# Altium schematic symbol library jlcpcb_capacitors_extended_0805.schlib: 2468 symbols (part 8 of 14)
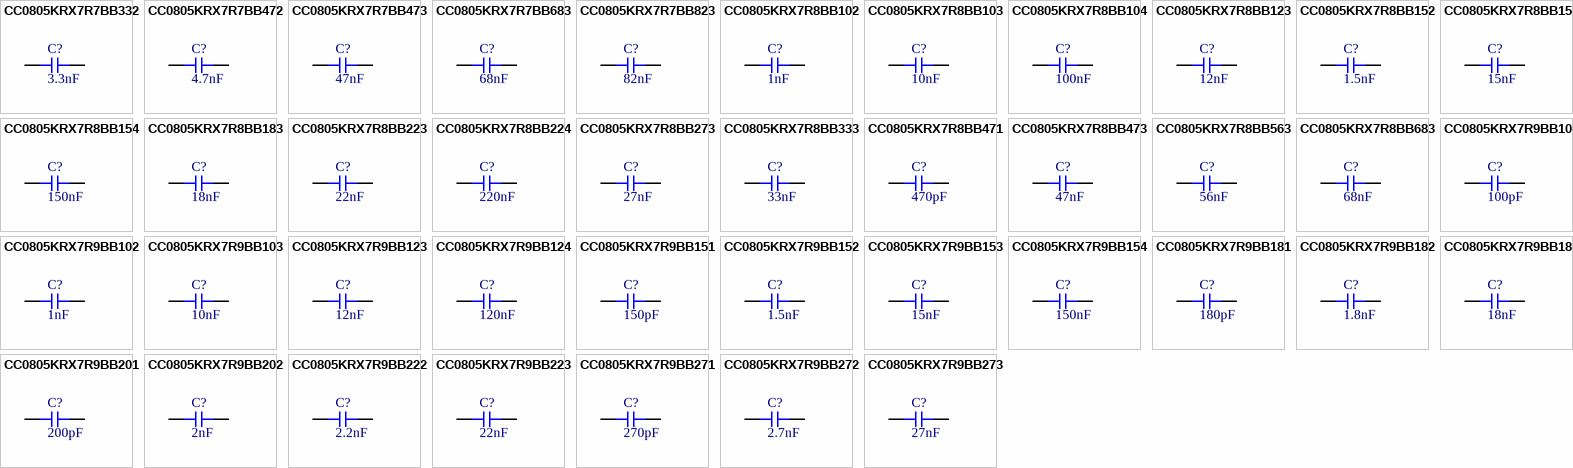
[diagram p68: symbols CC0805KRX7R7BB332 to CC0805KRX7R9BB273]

## CC0805KRX7R8BB102
designator C?  Capacitance: 1nF  (hidden comment: *)
Capacitor, Ceramic (MLCC), 1nF, ±10%, 25V, X7R, ±10%, SMD 0805; Manufacturer: YAGEO; Manufacturer Part Number: CC0805KRX7R8BB102
footprint CAP-0805 (0805 (2012M) Capacitor)
pins: 1, 2

## CC0805KRX7R8BB103
designator C?  Capacitance: 10nF  (hidden comment: *)
Capacitor, Ceramic (MLCC), 10nF, ±10%, 25V, X7R, ±10%, SMD 0805; Manufacturer: YAGEO; Manufacturer Part Number: CC0805KRX7R8BB103
footprint CAP-0805 (0805 (2012M) Capacitor)
pins: 1, 2

## CC0805KRX7R8BB104
designator C?  Capacitance: 100nF  (hidden comment: *)
Capacitor, Ceramic (MLCC), 100nF, ±10%, 25V, X7R, ±10%, SMD 0805; Manufacturer: YAGEO; Manufacturer Part Number: CC0805KRX7R8BB104
footprint CAP-0805 (0805 (2012M) Capacitor)
pins: 1, 2

## CC0805KRX7R8BB123
designator C?  Capacitance: 12nF  (hidden comment: *)
Capacitor, Ceramic (MLCC), 12nF, ±10%, 25V, X7R, ±10%, SMD 0805; Manufacturer: YAGEO; Manufacturer Part Number: CC0805KRX7R8BB123
footprint CAP-0805 (0805 (2012M) Capacitor)
pins: 1, 2

## CC0805KRX7R8BB152
designator C?  Capacitance: 1.5nF  (hidden comment: *)
Capacitor, Ceramic (MLCC), 1.5nF, ±10%, 25V, X7R, ±10%, SMD 0805; Manufacturer: YAGEO; Manufacturer Part Number: CC0805KRX7R8BB152
footprint CAP-0805 (0805 (2012M) Capacitor)
pins: 1, 2

## CC0805KRX7R8BB153
designator C?  Capacitance: 15nF  (hidden comment: *)
Capacitor, Ceramic (MLCC), 15nF, ±10%, 25V, X7R, ±10%, SMD 0805; Manufacturer: YAGEO; Manufacturer Part Number: CC0805KRX7R8BB153
footprint CAP-0805 (0805 (2012M) Capacitor)
pins: 1, 2

## CC0805KRX7R8BB154
designator C?  Capacitance: 150nF  (hidden comment: *)
Capacitor, Ceramic (MLCC), 150nF, ±10%, 25V, X7R, ±10%, SMD 0805; Manufacturer: YAGEO; Manufacturer Part Number: CC0805KRX7R8BB154
footprint CAP-0805 (0805 (2012M) Capacitor)
pins: 1, 2

## CC0805KRX7R8BB183
designator C?  Capacitance: 18nF  (hidden comment: *)
Capacitor, Ceramic (MLCC), 18nF, ±10%, 25V, X7R, ±10%, SMD 0805; Manufacturer: YAGEO; Manufacturer Part Number: CC0805KRX7R8BB183
footprint CAP-0805 (0805 (2012M) Capacitor)
pins: 1, 2

## CC0805KRX7R8BB223
designator C?  Capacitance: 22nF  (hidden comment: *)
Capacitor, Ceramic (MLCC), 22nF, ±10%, 25V, X7R, ±10%, SMD 0805; Manufacturer: YAGEO; Manufacturer Part Number: CC0805KRX7R8BB223
footprint CAP-0805 (0805 (2012M) Capacitor)
pins: 1, 2

## CC0805KRX7R8BB224
designator C?  Capacitance: 220nF  (hidden comment: *)
Capacitor, Ceramic (MLCC), 220nF, ±10%, 25V, X7R, ±10%, SMD 0805; Manufacturer: YAGEO; Manufacturer Part Number: CC0805KRX7R8BB224
footprint CAP-0805 (0805 (2012M) Capacitor)
pins: 1, 2

## CC0805KRX7R8BB273
designator C?  Capacitance: 27nF  (hidden comment: *)
Capacitor, Ceramic (MLCC), 27nF, ±10%, 25V, X7R, ±10%, SMD 0805; Manufacturer: YAGEO; Manufacturer Part Number: CC0805KRX7R8BB273
footprint CAP-0805 (0805 (2012M) Capacitor)
pins: 1, 2

## CC0805KRX7R8BB333
designator C?  Capacitance: 33nF  (hidden comment: *)
Capacitor, Ceramic (MLCC), 33nF, ±10%, 25V, X7R, ±10%, SMD 0805; Manufacturer: YAGEO; Manufacturer Part Number: CC0805KRX7R8BB333
footprint CAP-0805 (0805 (2012M) Capacitor)
pins: 1, 2

## CC0805KRX7R8BB471
designator C?  Capacitance: 470pF  (hidden comment: *)
Capacitor, Ceramic (MLCC), 470pF, ±10%, 25V, X7R, ±10%, SMD 0805; Manufacturer: YAGEO; Manufacturer Part Number: CC0805KRX7R8BB471
footprint CAP-0805 (0805 (2012M) Capacitor)
pins: 1, 2

## CC0805KRX7R8BB473
designator C?  Capacitance: 47nF  (hidden comment: *)
Capacitor, Ceramic (MLCC), 47nF, ±10%, 25V, X7R, ±10%, SMD 0805; Manufacturer: YAGEO; Manufacturer Part Number: CC0805KRX7R8BB473
footprint CAP-0805 (0805 (2012M) Capacitor)
pins: 1, 2

## CC0805KRX7R8BB563
designator C?  Capacitance: 56nF  (hidden comment: *)
Capacitor, Ceramic (MLCC), 56nF, ±10%, 25V, X7R, ±10%, SMD 0805; Manufacturer: YAGEO; Manufacturer Part Number: CC0805KRX7R8BB563
footprint CAP-0805 (0805 (2012M) Capacitor)
pins: 1, 2

## CC0805KRX7R8BB683
designator C?  Capacitance: 68nF  (hidden comment: *)
Capacitor, Ceramic (MLCC), 68nF, ±10%, 25V, X7R, ±10%, SMD 0805; Manufacturer: YAGEO; Manufacturer Part Number: CC0805KRX7R8BB683
footprint CAP-0805 (0805 (2012M) Capacitor)
pins: 1, 2

## CC0805KRX7R9BB101
designator C?  Capacitance: 100pF  (hidden comment: *)
Capacitor, Ceramic (MLCC), 100pF, ±10%, 50V, X7R, ±10%, SMD 0805; Manufacturer: YAGEO; Manufacturer Part Number: CC0805KRX7R9BB101
footprint CAP-0805 (0805 (2012M) Capacitor)
pins: 1, 2

## CC0805KRX7R9BB102
designator C?  Capacitance: 1nF  (hidden comment: *)
Capacitor, Ceramic (MLCC), 1nF, ±10%, 50V, X7R, ±10%, SMD 0805; Manufacturer: YAGEO; Manufacturer Part Number: CC0805KRX7R9BB102
footprint CAP-0805 (0805 (2012M) Capacitor)
pins: 1, 2

## CC0805KRX7R9BB103
designator C?  Capacitance: 10nF  (hidden comment: *)
Capacitor, Ceramic (MLCC), 10nF, ±10%, 50V, X7R, ±10%, SMD 0805; Manufacturer: YAGEO; Manufacturer Part Number: CC0805KRX7R9BB103
footprint CAP-0805 (0805 (2012M) Capacitor)
pins: 1, 2

## CC0805KRX7R9BB123
designator C?  Capacitance: 12nF  (hidden comment: *)
Capacitor, Ceramic (MLCC), 12nF, ±10%, 50V, X7R, ±10%, SMD 0805; Manufacturer: YAGEO; Manufacturer Part Number: CC0805KRX7R9BB123
footprint CAP-0805 (0805 (2012M) Capacitor)
pins: 1, 2

## CC0805KRX7R9BB124
designator C?  Capacitance: 120nF  (hidden comment: *)
Capacitor, Ceramic (MLCC), 120nF, ±10%, 50V, X7R, ±10%, SMD 0805; Manufacturer: YAGEO; Manufacturer Part Number: CC0805KRX7R9BB124
footprint CAP-0805 (0805 (2012M) Capacitor)
pins: 1, 2

## CC0805KRX7R9BB151
designator C?  Capacitance: 150pF  (hidden comment: *)
Capacitor, Ceramic (MLCC), 150pF, ±10%, 50V, X7R, ±10%, SMD 0805; Manufacturer: YAGEO; Manufacturer Part Number: CC0805KRX7R9BB151
footprint CAP-0805 (0805 (2012M) Capacitor)
pins: 1, 2

## CC0805KRX7R9BB152
designator C?  Capacitance: 1.5nF  (hidden comment: *)
Capacitor, Ceramic (MLCC), 1.5nF, ±10%, 50V, X7R, ±10%, SMD 0805; Manufacturer: YAGEO; Manufacturer Part Number: CC0805KRX7R9BB152
footprint CAP-0805 (0805 (2012M) Capacitor)
pins: 1, 2

## CC0805KRX7R9BB153
designator C?  Capacitance: 15nF  (hidden comment: *)
Capacitor, Ceramic (MLCC), 15nF, ±10%, 50V, X7R, ±10%, SMD 0805; Manufacturer: YAGEO; Manufacturer Part Number: CC0805KRX7R9BB153
footprint CAP-0805 (0805 (2012M) Capacitor)
pins: 1, 2

## CC0805KRX7R9BB154
designator C?  Capacitance: 150nF  (hidden comment: *)
Capacitor, Ceramic (MLCC), 150nF, ±10%, 50V, X7R, ±10%, SMD 0805; Manufacturer: YAGEO; Manufacturer Part Number: CC0805KRX7R9BB154
footprint CAP-0805 (0805 (2012M) Capacitor)
pins: 1, 2

## CC0805KRX7R9BB181
designator C?  Capacitance: 180pF  (hidden comment: *)
Capacitor, Ceramic (MLCC), 180pF, ±10%, 50V, X7R, ±10%, SMD 0805; Manufacturer: YAGEO; Manufacturer Part Number: CC0805KRX7R9BB181
footprint CAP-0805 (0805 (2012M) Capacitor)
pins: 1, 2

## CC0805KRX7R9BB182
designator C?  Capacitance: 1.8nF  (hidden comment: *)
Capacitor, Ceramic (MLCC), 1.8nF, ±10%, 50V, X7R, ±10%, SMD 0805; Manufacturer: YAGEO; Manufacturer Part Number: CC0805KRX7R9BB182
footprint CAP-0805 (0805 (2012M) Capacitor)
pins: 1, 2

## CC0805KRX7R9BB183
designator C?  Capacitance: 18nF  (hidden comment: *)
Capacitor, Ceramic (MLCC), 18nF, ±10%, 50V, X7R, ±10%, SMD 0805; Manufacturer: YAGEO; Manufacturer Part Number: CC0805KRX7R9BB183
footprint CAP-0805 (0805 (2012M) Capacitor)
pins: 1, 2

## CC0805KRX7R9BB201
designator C?  Capacitance: 200pF  (hidden comment: *)
Capacitor, Ceramic (MLCC), 200pF, ±10%, 50V, X7R, ±10%, SMD 0805; Manufacturer: YAGEO; Manufacturer Part Number: CC0805KRX7R9BB201
footprint CAP-0805 (0805 (2012M) Capacitor)
pins: 1, 2

## CC0805KRX7R9BB202
designator C?  Capacitance: 2nF  (hidden comment: *)
Capacitor, Ceramic (MLCC), 2nF, ±10%, 50V, X7R, ±10%, SMD 0805; Manufacturer: YAGEO; Manufacturer Part Number: CC0805KRX7R9BB202
footprint CAP-0805 (0805 (2012M) Capacitor)
pins: 1, 2

## CC0805KRX7R9BB222
designator C?  Capacitance: 2.2nF  (hidden comment: *)
Capacitor, Ceramic (MLCC), 2.2nF, ±10%, 50V, X7R, ±10%, SMD 0805; Manufacturer: YAGEO; Manufacturer Part Number: CC0805KRX7R9BB222
footprint CAP-0805 (0805 (2012M) Capacitor)
pins: 1, 2

## CC0805KRX7R9BB223
designator C?  Capacitance: 22nF  (hidden comment: *)
Capacitor, Ceramic (MLCC), 22nF, ±10%, 50V, X7R, ±10%, SMD 0805; Manufacturer: YAGEO; Manufacturer Part Number: CC0805KRX7R9BB223
footprint CAP-0805 (0805 (2012M) Capacitor)
pins: 1, 2

## CC0805KRX7R9BB271
designator C?  Capacitance: 270pF  (hidden comment: *)
Capacitor, Ceramic (MLCC), 270pF, ±10%, 50V, X7R, ±10%, SMD 0805; Manufacturer: YAGEO; Manufacturer Part Number: CC0805KRX7R9BB271
footprint CAP-0805 (0805 (2012M) Capacitor)
pins: 1, 2

## CC0805KRX7R9BB272
designator C?  Capacitance: 2.7nF  (hidden comment: *)
Capacitor, Ceramic (MLCC), 2.7nF, ±10%, 50V, X7R, ±10%, SMD 0805; Manufacturer: YAGEO; Manufacturer Part Number: CC0805KRX7R9BB272
footprint CAP-0805 (0805 (2012M) Capacitor)
pins: 1, 2

## CC0805KRX7R9BB273
designator C?  Capacitance: 27nF  (hidden comment: *)
Capacitor, Ceramic (MLCC), 27nF, ±10%, 50V, X7R, ±10%, SMD 0805; Manufacturer: YAGEO; Manufacturer Part Number: CC0805KRX7R9BB273
footprint CAP-0805 (0805 (2012M) Capacitor)
pins: 1, 2

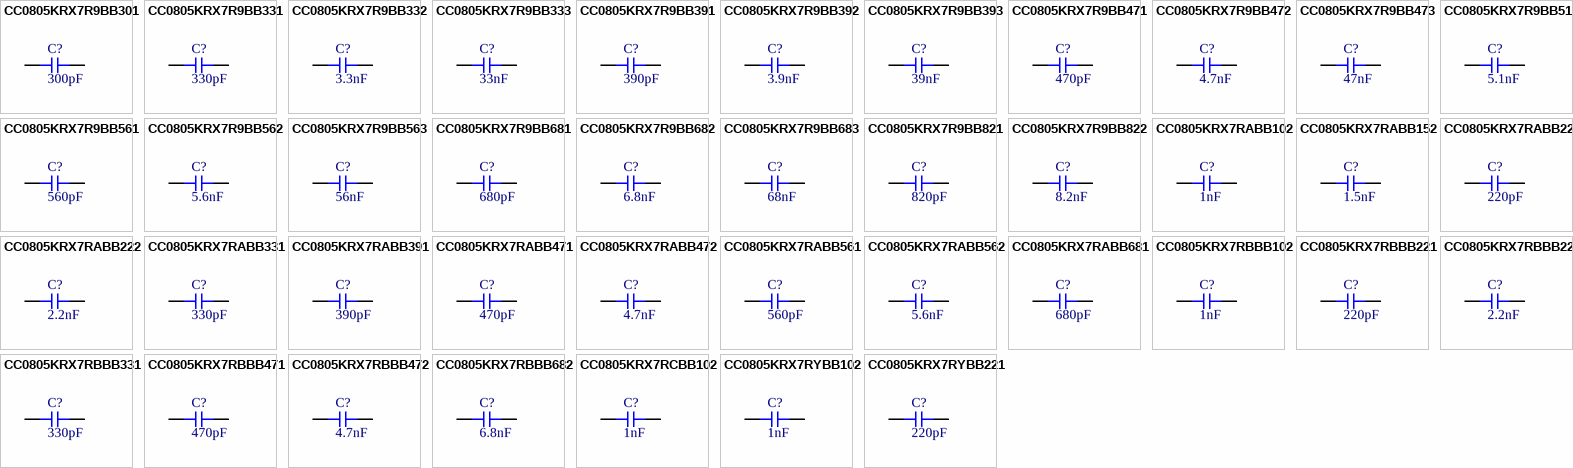
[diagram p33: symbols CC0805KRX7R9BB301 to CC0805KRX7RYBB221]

## CC0805KRX7R9BB301
designator C?  Capacitance: 300pF  (hidden comment: *)
Capacitor, Ceramic (MLCC), 300pF, ±10%, 50V, X7R, ±10%, SMD 0805; Manufacturer: YAGEO; Manufacturer Part Number: CC0805KRX7R9BB301
footprint CAP-0805 (0805 (2012M) Capacitor)
pins: 1, 2

## CC0805KRX7R9BB331
designator C?  Capacitance: 330pF  (hidden comment: *)
Capacitor, Ceramic (MLCC), 330pF, ±10%, 50V, X7R, ±10%, SMD 0805; Manufacturer: YAGEO; Manufacturer Part Number: CC0805KRX7R9BB331
footprint CAP-0805 (0805 (2012M) Capacitor)
pins: 1, 2

## CC0805KRX7R9BB332
designator C?  Capacitance: 3.3nF  (hidden comment: *)
Capacitor, Ceramic (MLCC), 3.3nF, ±10%, 50V, X7R, ±10%, SMD 0805; Manufacturer: YAGEO; Manufacturer Part Number: CC0805KRX7R9BB332
footprint CAP-0805 (0805 (2012M) Capacitor)
pins: 1, 2

## CC0805KRX7R9BB333
designator C?  Capacitance: 33nF  (hidden comment: *)
Capacitor, Ceramic (MLCC), 33nF, ±10%, 50V, X7R, ±10%, SMD 0805; Manufacturer: YAGEO; Manufacturer Part Number: CC0805KRX7R9BB333
footprint CAP-0805 (0805 (2012M) Capacitor)
pins: 1, 2

## CC0805KRX7R9BB391
designator C?  Capacitance: 390pF  (hidden comment: *)
Capacitor, Ceramic (MLCC), 390pF, ±10%, 50V, X7R, ±10%, SMD 0805; Manufacturer: YAGEO; Manufacturer Part Number: CC0805KRX7R9BB391
footprint CAP-0805 (0805 (2012M) Capacitor)
pins: 1, 2

## CC0805KRX7R9BB392
designator C?  Capacitance: 3.9nF  (hidden comment: *)
Capacitor, Ceramic (MLCC), 3.9nF, ±10%, 50V, X7R, ±10%, SMD 0805; Manufacturer: YAGEO; Manufacturer Part Number: CC0805KRX7R9BB392
footprint CAP-0805 (0805 (2012M) Capacitor)
pins: 1, 2

## CC0805KRX7R9BB393
designator C?  Capacitance: 39nF  (hidden comment: *)
Capacitor, Ceramic (MLCC), 39nF, ±10%, 50V, X7R, ±10%, SMD 0805; Manufacturer: YAGEO; Manufacturer Part Number: CC0805KRX7R9BB393
footprint CAP-0805 (0805 (2012M) Capacitor)
pins: 1, 2

## CC0805KRX7R9BB471
designator C?  Capacitance: 470pF  (hidden comment: *)
Capacitor, Ceramic (MLCC), 470pF, ±10%, 50V, X7R, ±10%, SMD 0805; Manufacturer: YAGEO; Manufacturer Part Number: CC0805KRX7R9BB471
footprint CAP-0805 (0805 (2012M) Capacitor)
pins: 1, 2

## CC0805KRX7R9BB472
designator C?  Capacitance: 4.7nF  (hidden comment: *)
Capacitor, Ceramic (MLCC), 4.7nF, ±10%, 50V, X7R, ±10%, SMD 0805; Manufacturer: YAGEO; Manufacturer Part Number: CC0805KRX7R9BB472
footprint CAP-0805 (0805 (2012M) Capacitor)
pins: 1, 2

## CC0805KRX7R9BB473
designator C?  Capacitance: 47nF  (hidden comment: *)
Capacitor, Ceramic (MLCC), 47nF, ±10%, 50V, X7R, ±10%, SMD 0805; Manufacturer: YAGEO; Manufacturer Part Number: CC0805KRX7R9BB473
footprint CAP-0805 (0805 (2012M) Capacitor)
pins: 1, 2

## CC0805KRX7R9BB512
designator C?  Capacitance: 5.1nF  (hidden comment: *)
Capacitor, Ceramic (MLCC), 5.1nF, ±10%, 50V, X7R, ±10%, SMD 0805; Manufacturer: YAGEO; Manufacturer Part Number: CC0805KRX7R9BB512
footprint CAP-0805 (0805 (2012M) Capacitor)
pins: 1, 2

## CC0805KRX7R9BB561
designator C?  Capacitance: 560pF  (hidden comment: *)
Capacitor, Ceramic (MLCC), 560pF, ±10%, 50V, X7R, ±10%, SMD 0805; Manufacturer: YAGEO; Manufacturer Part Number: CC0805KRX7R9BB561
footprint CAP-0805 (0805 (2012M) Capacitor)
pins: 1, 2

## CC0805KRX7R9BB562
designator C?  Capacitance: 5.6nF  (hidden comment: *)
Capacitor, Ceramic (MLCC), 5.6nF, ±10%, 50V, X7R, ±10%, SMD 0805; Manufacturer: YAGEO; Manufacturer Part Number: CC0805KRX7R9BB562
footprint CAP-0805 (0805 (2012M) Capacitor)
pins: 1, 2

## CC0805KRX7R9BB563
designator C?  Capacitance: 56nF  (hidden comment: *)
Capacitor, Ceramic (MLCC), 56nF, ±10%, 50V, X7R, ±10%, SMD 0805; Manufacturer: YAGEO; Manufacturer Part Number: CC0805KRX7R9BB563
footprint CAP-0805 (0805 (2012M) Capacitor)
pins: 1, 2

## CC0805KRX7R9BB681
designator C?  Capacitance: 680pF  (hidden comment: *)
Capacitor, Ceramic (MLCC), 680pF, ±10%, 50V, X7R, ±10%, SMD 0805; Manufacturer: YAGEO; Manufacturer Part Number: CC0805KRX7R9BB681
footprint CAP-0805 (0805 (2012M) Capacitor)
pins: 1, 2

## CC0805KRX7R9BB682
designator C?  Capacitance: 6.8nF  (hidden comment: *)
Capacitor, Ceramic (MLCC), 6.8nF, ±10%, 50V, X7R, ±10%, SMD 0805; Manufacturer: YAGEO; Manufacturer Part Number: CC0805KRX7R9BB682
footprint CAP-0805 (0805 (2012M) Capacitor)
pins: 1, 2

## CC0805KRX7R9BB683
designator C?  Capacitance: 68nF  (hidden comment: *)
Capacitor, Ceramic (MLCC), 68nF, ±10%, 50V, X7R, ±10%, SMD 0805; Manufacturer: YAGEO; Manufacturer Part Number: CC0805KRX7R9BB683
footprint CAP-0805 (0805 (2012M) Capacitor)
pins: 1, 2

## CC0805KRX7R9BB821
designator C?  Capacitance: 820pF  (hidden comment: *)
Capacitor, Ceramic (MLCC), 820pF, ±10%, 50V, X7R, ±10%, SMD 0805; Manufacturer: YAGEO; Manufacturer Part Number: CC0805KRX7R9BB821
footprint CAP-0805 (0805 (2012M) Capacitor)
pins: 1, 2

## CC0805KRX7R9BB822
designator C?  Capacitance: 8.2nF  (hidden comment: *)
Capacitor, Ceramic (MLCC), 8.2nF, ±10%, 50V, X7R, ±10%, SMD 0805; Manufacturer: YAGEO; Manufacturer Part Number: CC0805KRX7R9BB822
footprint CAP-0805 (0805 (2012M) Capacitor)
pins: 1, 2

## CC0805KRX7RABB102
designator C?  Capacitance: 1nF  (hidden comment: *)
Capacitor, Ceramic (MLCC), 1nF, ±10%, 200V, X7R, ±10%, SMD 0805; Manufacturer: YAGEO; Manufacturer Part Number: CC0805KRX7RABB102
footprint CAP-0805 (0805 (2012M) Capacitor)
pins: 1, 2

## CC0805KRX7RABB152
designator C?  Capacitance: 1.5nF  (hidden comment: *)
Capacitor, Ceramic (MLCC), 1.5nF, ±10%, 200V, X7R, ±10%, SMD 0805; Manufacturer: YAGEO; Manufacturer Part Number: CC0805KRX7RABB152
footprint CAP-0805 (0805 (2012M) Capacitor)
pins: 1, 2

## CC0805KRX7RABB221
designator C?  Capacitance: 220pF  (hidden comment: *)
Capacitor, Ceramic (MLCC), 220pF, ±10%, 200V, X7R, ±10%, SMD 0805; Manufacturer: YAGEO; Manufacturer Part Number: CC0805KRX7RABB221
footprint CAP-0805 (0805 (2012M) Capacitor)
pins: 1, 2

## CC0805KRX7RABB222
designator C?  Capacitance: 2.2nF  (hidden comment: *)
Capacitor, Ceramic (MLCC), 2.2nF, ±10%, 200V, X7R, ±10%, SMD 0805; Manufacturer: YAGEO; Manufacturer Part Number: CC0805KRX7RABB222
footprint CAP-0805 (0805 (2012M) Capacitor)
pins: 1, 2

## CC0805KRX7RABB331
designator C?  Capacitance: 330pF  (hidden comment: *)
Capacitor, Ceramic (MLCC), 330pF, ±10%, 200V, X7R, ±10%, SMD 0805; Manufacturer: YAGEO; Manufacturer Part Number: CC0805KRX7RABB331
footprint CAP-0805 (0805 (2012M) Capacitor)
pins: 1, 2

## CC0805KRX7RABB391
designator C?  Capacitance: 390pF  (hidden comment: *)
Capacitor, Ceramic (MLCC), 390pF, ±10%, 200V, X7R, ±10%, SMD 0805; Manufacturer: YAGEO; Manufacturer Part Number: CC0805KRX7RABB391
footprint CAP-0805 (0805 (2012M) Capacitor)
pins: 1, 2

## CC0805KRX7RABB471
designator C?  Capacitance: 470pF  (hidden comment: *)
Capacitor, Ceramic (MLCC), 470pF, ±10%, 200V, X7R, ±10%, SMD 0805; Manufacturer: YAGEO; Manufacturer Part Number: CC0805KRX7RABB471
footprint CAP-0805 (0805 (2012M) Capacitor)
pins: 1, 2

## CC0805KRX7RABB472
designator C?  Capacitance: 4.7nF  (hidden comment: *)
Capacitor, Ceramic (MLCC), 4.7nF, ±10%, 200V, X7R, ±10%, SMD 0805; Manufacturer: YAGEO; Manufacturer Part Number: CC0805KRX7RABB472
footprint CAP-0805 (0805 (2012M) Capacitor)
pins: 1, 2

## CC0805KRX7RABB561
designator C?  Capacitance: 560pF  (hidden comment: *)
Capacitor, Ceramic (MLCC), 560pF, ±10%, 200V, X7R, ±10%, SMD 0805; Manufacturer: YAGEO; Manufacturer Part Number: CC0805KRX7RABB561
footprint CAP-0805 (0805 (2012M) Capacitor)
pins: 1, 2

## CC0805KRX7RABB562
designator C?  Capacitance: 5.6nF  (hidden comment: *)
Capacitor, Ceramic (MLCC), 5.6nF, ±10%, 200V, X7R, ±10%, SMD 0805; Manufacturer: YAGEO; Manufacturer Part Number: CC0805KRX7RABB562
footprint CAP-0805 (0805 (2012M) Capacitor)
pins: 1, 2

## CC0805KRX7RABB681
designator C?  Capacitance: 680pF  (hidden comment: *)
Capacitor, Ceramic (MLCC), 680pF, ±10%, 200V, X7R, ±10%, SMD 0805; Manufacturer: YAGEO; Manufacturer Part Number: CC0805KRX7RABB681
footprint CAP-0805 (0805 (2012M) Capacitor)
pins: 1, 2

## CC0805KRX7RBBB102
designator C?  Capacitance: 1nF  (hidden comment: *)
Capacitor, Ceramic (MLCC), 1nF, ±10%, 500V, X7R, ±10%, SMD 0805; Manufacturer: YAGEO; Manufacturer Part Number: CC0805KRX7RBBB102
footprint CAP-0805 (0805 (2012M) Capacitor)
pins: 1, 2

## CC0805KRX7RBBB221
designator C?  Capacitance: 220pF  (hidden comment: *)
Capacitor, Ceramic (MLCC), 220pF, ±10%, 500V, X7R, ±10%, SMD 0805; Manufacturer: YAGEO; Manufacturer Part Number: CC0805KRX7RBBB221
footprint CAP-0805 (0805 (2012M) Capacitor)
pins: 1, 2

## CC0805KRX7RBBB222
designator C?  Capacitance: 2.2nF  (hidden comment: *)
Capacitor, Ceramic (MLCC), 2.2nF, ±10%, 500V, X7R, ±10%, SMD 0805; Manufacturer: YAGEO; Manufacturer Part Number: CC0805KRX7RBBB222
footprint CAP-0805 (0805 (2012M) Capacitor)
pins: 1, 2

## CC0805KRX7RBBB331
designator C?  Capacitance: 330pF  (hidden comment: *)
Capacitor, Ceramic (MLCC), 330pF, ±10%, 500V, X7R, ±10%, SMD 0805; Manufacturer: YAGEO; Manufacturer Part Number: CC0805KRX7RBBB331
footprint CAP-0805 (0805 (2012M) Capacitor)
pins: 1, 2

## CC0805KRX7RBBB471
designator C?  Capacitance: 470pF  (hidden comment: *)
Capacitor, Ceramic (MLCC), 470pF, ±10%, 500V, X7R, ±10%, SMD 0805; Manufacturer: YAGEO; Manufacturer Part Number: CC0805KRX7RBBB471
footprint CAP-0805 (0805 (2012M) Capacitor)
pins: 1, 2

## CC0805KRX7RBBB472
designator C?  Capacitance: 4.7nF  (hidden comment: *)
Capacitor, Ceramic (MLCC), 4.7nF, ±10%, 500V, X7R, ±10%, SMD 0805; Manufacturer: YAGEO; Manufacturer Part Number: CC0805KRX7RBBB472
footprint CAP-0805 (0805 (2012M) Capacitor)
pins: 1, 2

## CC0805KRX7RBBB682
designator C?  Capacitance: 6.8nF  (hidden comment: *)
Capacitor, Ceramic (MLCC), 6.8nF, ±10%, 500V, X7R, ±10%, SMD 0805; Manufacturer: YAGEO; Manufacturer Part Number: CC0805KRX7RBBB682
footprint CAP-0805 (0805 (2012M) Capacitor)
pins: 1, 2

## CC0805KRX7RCBB102
designator C?  Capacitance: 1nF  (hidden comment: *)
Capacitor, Ceramic (MLCC), 1nF, ±10%, 1kV, X7R, ±10%, SMD 0805; Manufacturer: YAGEO; Manufacturer Part Number: CC0805KRX7RCBB102
footprint CAP-0805 (0805 (2012M) Capacitor)
pins: 1, 2

## CC0805KRX7RYBB102
designator C?  Capacitance: 1nF  (hidden comment: *)
Capacitor, Ceramic (MLCC), 1nF, ±10%, 250V, X7R, ±10%, SMD 0805; Manufacturer: YAGEO; Manufacturer Part Number: CC0805KRX7RYBB102
footprint CAP-0805 (0805 (2012M) Capacitor)
pins: 1, 2

## CC0805KRX7RYBB221
designator C?  Capacitance: 220pF  (hidden comment: *)
Capacitor, Ceramic (MLCC), 220pF, ±10%, 250V, X7R, ±10%, SMD 0805; Manufacturer: YAGEO; Manufacturer Part Number: CC0805KRX7RYBB221
footprint CAP-0805 (0805 (2012M) Capacitor)
pins: 1, 2

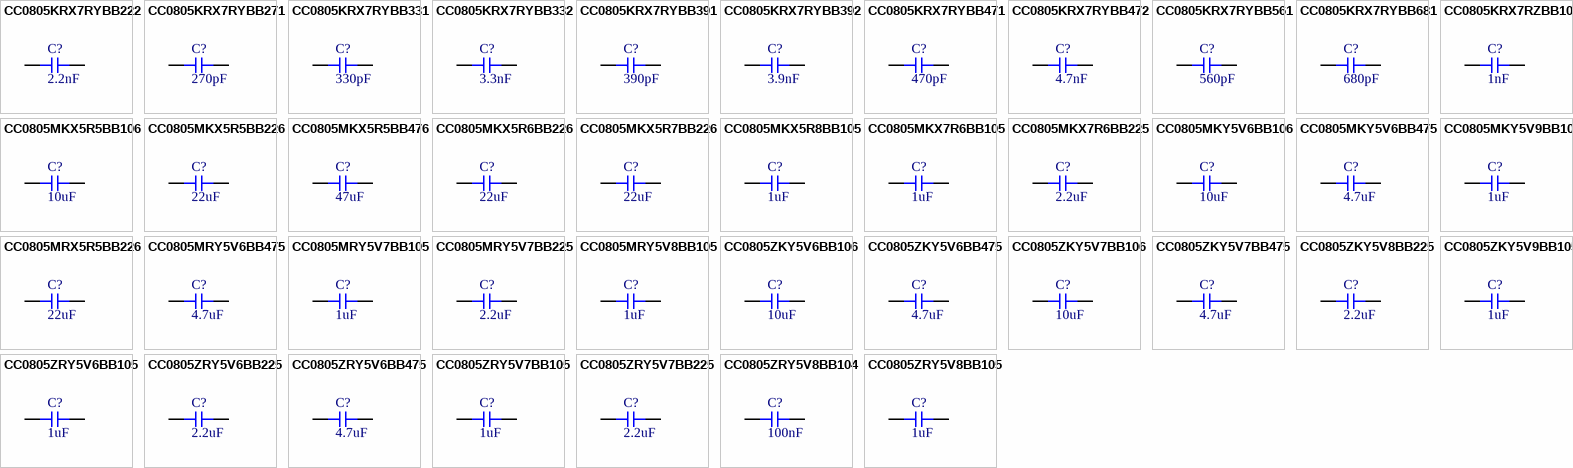
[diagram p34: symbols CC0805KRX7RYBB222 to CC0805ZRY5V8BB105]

## CC0805KRX7RYBB222
designator C?  Capacitance: 2.2nF  (hidden comment: *)
Capacitor, Ceramic (MLCC), 2.2nF, ±10%, 250V, X7R, ±10%, SMD 0805; Manufacturer: YAGEO; Manufacturer Part Number: CC0805KRX7RYBB222
footprint CAP-0805 (0805 (2012M) Capacitor)
pins: 1, 2

## CC0805KRX7RYBB271
designator C?  Capacitance: 270pF  (hidden comment: *)
Capacitor, Ceramic (MLCC), 270pF, ±10%, 250V, X7R, ±10%, SMD 0805; Manufacturer: YAGEO; Manufacturer Part Number: CC0805KRX7RYBB271
footprint CAP-0805 (0805 (2012M) Capacitor)
pins: 1, 2

## CC0805KRX7RYBB331
designator C?  Capacitance: 330pF  (hidden comment: *)
Capacitor, Ceramic (MLCC), 330pF, ±10%, 250V, X7R, ±10%, SMD 0805; Manufacturer: YAGEO; Manufacturer Part Number: CC0805KRX7RYBB331
footprint CAP-0805 (0805 (2012M) Capacitor)
pins: 1, 2

## CC0805KRX7RYBB332
designator C?  Capacitance: 3.3nF  (hidden comment: *)
Capacitor, Ceramic (MLCC), 3.3nF, ±10%, 250V, X7R, ±10%, SMD 0805; Manufacturer: YAGEO; Manufacturer Part Number: CC0805KRX7RYBB332
footprint CAP-0805 (0805 (2012M) Capacitor)
pins: 1, 2

## CC0805KRX7RYBB391
designator C?  Capacitance: 390pF  (hidden comment: *)
Capacitor, Ceramic (MLCC), 390pF, ±10%, 250V, X7R, ±10%, SMD 0805; Manufacturer: YAGEO; Manufacturer Part Number: CC0805KRX7RYBB391
footprint CAP-0805 (0805 (2012M) Capacitor)
pins: 1, 2

## CC0805KRX7RYBB392
designator C?  Capacitance: 3.9nF  (hidden comment: *)
Capacitor, Ceramic (MLCC), 3.9nF, ±10%, 250V, X7R, ±10%, SMD 0805; Manufacturer: YAGEO; Manufacturer Part Number: CC0805KRX7RYBB392
footprint CAP-0805 (0805 (2012M) Capacitor)
pins: 1, 2

## CC0805KRX7RYBB471
designator C?  Capacitance: 470pF  (hidden comment: *)
Capacitor, Ceramic (MLCC), 470pF, ±10%, 250V, X7R, ±10%, SMD 0805; Manufacturer: YAGEO; Manufacturer Part Number: CC0805KRX7RYBB471
footprint CAP-0805 (0805 (2012M) Capacitor)
pins: 1, 2

## CC0805KRX7RYBB472
designator C?  Capacitance: 4.7nF  (hidden comment: *)
Capacitor, Ceramic (MLCC), 4.7nF, ±10%, 250V, X7R, ±10%, SMD 0805; Manufacturer: YAGEO; Manufacturer Part Number: CC0805KRX7RYBB472
footprint CAP-0805 (0805 (2012M) Capacitor)
pins: 1, 2

## CC0805KRX7RYBB561
designator C?  Capacitance: 560pF  (hidden comment: *)
Capacitor, Ceramic (MLCC), 560pF, ±10%, 250V, X7R, ±10%, SMD 0805; Manufacturer: YAGEO; Manufacturer Part Number: CC0805KRX7RYBB561
footprint CAP-0805 (0805 (2012M) Capacitor)
pins: 1, 2

## CC0805KRX7RYBB681
designator C?  Capacitance: 680pF  (hidden comment: *)
Capacitor, Ceramic (MLCC), 680pF, ±10%, 250V, X7R, ±10%, SMD 0805; Manufacturer: YAGEO; Manufacturer Part Number: CC0805KRX7RYBB681
footprint CAP-0805 (0805 (2012M) Capacitor)
pins: 1, 2

## CC0805KRX7RZBB102
designator C?  Capacitance: 1nF  (hidden comment: *)
Capacitor, Ceramic (MLCC), 1nF, ±10%, 630V, X7R, ±10%, SMD 0805; Manufacturer: YAGEO; Manufacturer Part Number: CC0805KRX7RZBB102
footprint CAP-0805 (0805 (2012M) Capacitor)
pins: 1, 2

## CC0805MKX5R5BB106
designator C?  Capacitance: 10uF  (hidden comment: *)
Capacitor, Ceramic (MLCC), 10uF, ±20%, 6.3V, X5R, ±20%, SMD 0805; Manufacturer: YAGEO; Manufacturer Part Number: CC0805MKX5R5BB106
footprint CAP-0805 (0805 (2012M) Capacitor)
pins: 1, 2

## CC0805MKX5R5BB226
designator C?  Capacitance: 22uF  (hidden comment: *)
Capacitor, Ceramic (MLCC), 22uF, ±20%, 6.3V, X5R, ±20%, SMD 0805; Manufacturer: YAGEO; Manufacturer Part Number: CC0805MKX5R5BB226
footprint CAP-0805 (0805 (2012M) Capacitor)
pins: 1, 2

## CC0805MKX5R5BB476
designator C?  Capacitance: 47uF  (hidden comment: *)
Capacitor, Ceramic (MLCC), 47uF, ±20%, 6.3V, X5R, ±20%, SMD 0805; Manufacturer: YAGEO; Manufacturer Part Number: CC0805MKX5R5BB476
footprint CAP-0805 (0805 (2012M) Capacitor)
pins: 1, 2

## CC0805MKX5R6BB226
designator C?  Capacitance: 22uF  (hidden comment: *)
Capacitor, Ceramic (MLCC), 22uF, ±20%, 10V, X5R, ±20%, SMD 0805; Manufacturer: YAGEO; Manufacturer Part Number: CC0805MKX5R6BB226
footprint CAP-0805 (0805 (2012M) Capacitor)
pins: 1, 2

## CC0805MKX5R7BB226
designator C?  Capacitance: 22uF  (hidden comment: *)
Capacitor, Ceramic (MLCC), 22uF, ±20%, 16V, X5R, ±20%, SMD 0805; Manufacturer: YAGEO; Manufacturer Part Number: CC0805MKX5R7BB226
footprint CAP-0805 (0805 (2012M) Capacitor)
pins: 1, 2

## CC0805MKX5R8BB105
designator C?  Capacitance: 1uF  (hidden comment: *)
Capacitor, Ceramic (MLCC), 1uF, ±20%, 25V, X5R, ±20%, SMD 0805; Manufacturer: YAGEO; Manufacturer Part Number: CC0805MKX5R8BB105
footprint CAP-0805 (0805 (2012M) Capacitor)
pins: 1, 2

## CC0805MKX7R6BB105
designator C?  Capacitance: 1uF  (hidden comment: *)
Capacitor, Ceramic (MLCC), 1uF, ±20%, 10V, X7R, ±20%, SMD 0805; Manufacturer: YAGEO; Manufacturer Part Number: CC0805MKX7R6BB105
footprint CAP-0805 (0805 (2012M) Capacitor)
pins: 1, 2

## CC0805MKX7R6BB225
designator C?  Capacitance: 2.2uF  (hidden comment: *)
Capacitor, Ceramic (MLCC), 2.2uF, ±20%, 10V, X7R, ±20%, SMD 0805; Manufacturer: YAGEO; Manufacturer Part Number: CC0805MKX7R6BB225
footprint CAP-0805 (0805 (2012M) Capacitor)
pins: 1, 2

## CC0805MKY5V6BB106
designator C?  Capacitance: 10uF  (hidden comment: *)
Capacitor, Ceramic (MLCC), 10uF, ±20%, 10V, Y5V, ±20%, SMD 0805; Manufacturer: YAGEO; Manufacturer Part Number: CC0805MKY5V6BB106
footprint CAP-0805 (0805 (2012M) Capacitor)
pins: 1, 2

## CC0805MKY5V6BB475
designator C?  Capacitance: 4.7uF  (hidden comment: *)
Capacitor, Ceramic (MLCC), 4.7uF, ±20%, 10V, Y5V, ±20%, SMD 0805; Manufacturer: YAGEO; Manufacturer Part Number: CC0805MKY5V6BB475
footprint CAP-0805 (0805 (2012M) Capacitor)
pins: 1, 2

## CC0805MKY5V9BB105
designator C?  Capacitance: 1uF  (hidden comment: *)
Capacitor, Ceramic (MLCC), 1uF, ±20%, 50V, Y5V, ±20%, SMD 0805; Manufacturer: YAGEO; Manufacturer Part Number: CC0805MKY5V9BB105
footprint CAP-0805 (0805 (2012M) Capacitor)
pins: 1, 2

## CC0805MRX5R5BB226
designator C?  Capacitance: 22uF  (hidden comment: *)
Capacitor, Ceramic (MLCC), 22uF, ±20%, 6.3V, X5R, ±20%, SMD 0805; Manufacturer: YAGEO; Manufacturer Part Number: CC0805MRX5R5BB226
footprint CAP-0805 (0805 (2012M) Capacitor)
pins: 1, 2

## CC0805MRY5V6BB475
designator C?  Capacitance: 4.7uF  (hidden comment: *)
Capacitor, Ceramic (MLCC), 4.7uF, ±20%, 10V, Y5V, ±20%, SMD 0805; Manufacturer: YAGEO; Manufacturer Part Number: CC0805MRY5V6BB475
footprint CAP-0805 (0805 (2012M) Capacitor)
pins: 1, 2

## CC0805MRY5V7BB105
designator C?  Capacitance: 1uF  (hidden comment: *)
Capacitor, Ceramic (MLCC), 1uF, ±20%, 16V, Y5V, ±20%, SMD 0805; Manufacturer: YAGEO; Manufacturer Part Number: CC0805MRY5V7BB105
footprint CAP-0805 (0805 (2012M) Capacitor)
pins: 1, 2

## CC0805MRY5V7BB225
designator C?  Capacitance: 2.2uF  (hidden comment: *)
Capacitor, Ceramic (MLCC), 2.2uF, ±20%, 16V, Y5V, ±20%, SMD 0805; Manufacturer: YAGEO; Manufacturer Part Number: CC0805MRY5V7BB225
footprint CAP-0805 (0805 (2012M) Capacitor)
pins: 1, 2

## CC0805MRY5V8BB105
designator C?  Capacitance: 1uF  (hidden comment: *)
Capacitor, Ceramic (MLCC), 1uF, ±20%, 25V, Y5V, ±20%, SMD 0805; Manufacturer: YAGEO; Manufacturer Part Number: CC0805MRY5V8BB105
footprint CAP-0805 (0805 (2012M) Capacitor)
pins: 1, 2

## CC0805ZKY5V6BB106
designator C?  Capacitance: 10uF  (hidden comment: *)
Capacitor, Ceramic (MLCC), 10uF, 10V, Y5V, SMD 0805; Manufacturer: YAGEO; Manufacturer Part Number: CC0805ZKY5V6BB106; Temperature Rating: -20%~+80%
footprint CAP-0805 (0805 (2012M) Capacitor)
pins: 1, 2

## CC0805ZKY5V6BB475
designator C?  Capacitance: 4.7uF  (hidden comment: *)
Capacitor, Ceramic (MLCC), 4.7uF, 10V, Y5V, SMD 0805; Manufacturer: YAGEO; Manufacturer Part Number: CC0805ZKY5V6BB475; Temperature Rating: -20%~+80%
footprint CAP-0805 (0805 (2012M) Capacitor)
pins: 1, 2

## CC0805ZKY5V7BB106
designator C?  Capacitance: 10uF  (hidden comment: *)
Capacitor, Ceramic (MLCC), 10uF, 16V, Y5V, SMD 0805; Manufacturer: YAGEO; Manufacturer Part Number: CC0805ZKY5V7BB106; Temperature Rating: -20%~+80%
footprint CAP-0805 (0805 (2012M) Capacitor)
pins: 1, 2

## CC0805ZKY5V7BB475
designator C?  Capacitance: 4.7uF  (hidden comment: *)
Capacitor, Ceramic (MLCC), 4.7uF, 16V, Y5V, SMD 0805; Manufacturer: YAGEO; Manufacturer Part Number: CC0805ZKY5V7BB475; Temperature Rating: -20%~+80%
footprint CAP-0805 (0805 (2012M) Capacitor)
pins: 1, 2

## CC0805ZKY5V8BB225
designator C?  Capacitance: 2.2uF  (hidden comment: *)
Capacitor, Ceramic (MLCC), 2.2uF, 25V, Y5V, SMD 0805; Manufacturer: YAGEO; Manufacturer Part Number: CC0805ZKY5V8BB225; Temperature Rating: -20%~+80%
footprint CAP-0805 (0805 (2012M) Capacitor)
pins: 1, 2

## CC0805ZKY5V9BB105
designator C?  Capacitance: 1uF  (hidden comment: *)
Capacitor, Ceramic (MLCC), 1uF, 50V, Y5V, SMD 0805; Manufacturer: YAGEO; Manufacturer Part Number: CC0805ZKY5V9BB105; Temperature Rating: -20%~+80%
footprint CAP-0805 (0805 (2012M) Capacitor)
pins: 1, 2

## CC0805ZRY5V6BB105
designator C?  Capacitance: 1uF  (hidden comment: *)
Capacitor, Ceramic (MLCC), 1uF, 10V, Y5V, SMD 0805; Manufacturer: YAGEO; Manufacturer Part Number: CC0805ZRY5V6BB105; Temperature Rating: -20%~+80%
footprint CAP-0805 (0805 (2012M) Capacitor)
pins: 1, 2

## CC0805ZRY5V6BB225
designator C?  Capacitance: 2.2uF  (hidden comment: *)
Capacitor, Ceramic (MLCC), 2.2uF, 10V, Y5V, SMD 0805; Manufacturer: YAGEO; Manufacturer Part Number: CC0805ZRY5V6BB225; Temperature Rating: -20%~+80%
footprint CAP-0805 (0805 (2012M) Capacitor)
pins: 1, 2

## CC0805ZRY5V6BB475
designator C?  Capacitance: 4.7uF  (hidden comment: *)
Capacitor, Ceramic (MLCC), 4.7uF, 10V, Y5V, SMD 0805; Manufacturer: YAGEO; Manufacturer Part Number: CC0805ZRY5V6BB475; Temperature Rating: -20%~+80%
footprint CAP-0805 (0805 (2012M) Capacitor)
pins: 1, 2

## CC0805ZRY5V7BB105
designator C?  Capacitance: 1uF  (hidden comment: *)
Capacitor, Ceramic (MLCC), 1uF, 16V, Y5V, SMD 0805; Manufacturer: YAGEO; Manufacturer Part Number: CC0805ZRY5V7BB105; Temperature Rating: -20%~+80%
footprint CAP-0805 (0805 (2012M) Capacitor)
pins: 1, 2

## CC0805ZRY5V7BB225
designator C?  Capacitance: 2.2uF  (hidden comment: *)
Capacitor, Ceramic (MLCC), 2.2uF, 16V, Y5V, SMD 0805; Manufacturer: YAGEO; Manufacturer Part Number: CC0805ZRY5V7BB225; Temperature Rating: -20%~+80%
footprint CAP-0805 (0805 (2012M) Capacitor)
pins: 1, 2

## CC0805ZRY5V8BB104
designator C?  Capacitance: 100nF  (hidden comment: *)
Capacitor, Ceramic (MLCC), 100nF, 25V, Y5V, SMD 0805; Manufacturer: YAGEO; Manufacturer Part Number: CC0805ZRY5V8BB104; Temperature Rating: -20%~+80%
footprint CAP-0805 (0805 (2012M) Capacitor)
pins: 1, 2

## CC0805ZRY5V8BB105
designator C?  Capacitance: 1uF  (hidden comment: *)
Capacitor, Ceramic (MLCC), 1uF, 25V, Y5V, SMD 0805; Manufacturer: YAGEO; Manufacturer Part Number: CC0805ZRY5V8BB105; Temperature Rating: -20%~+80%
footprint CAP-0805 (0805 (2012M) Capacitor)
pins: 1, 2

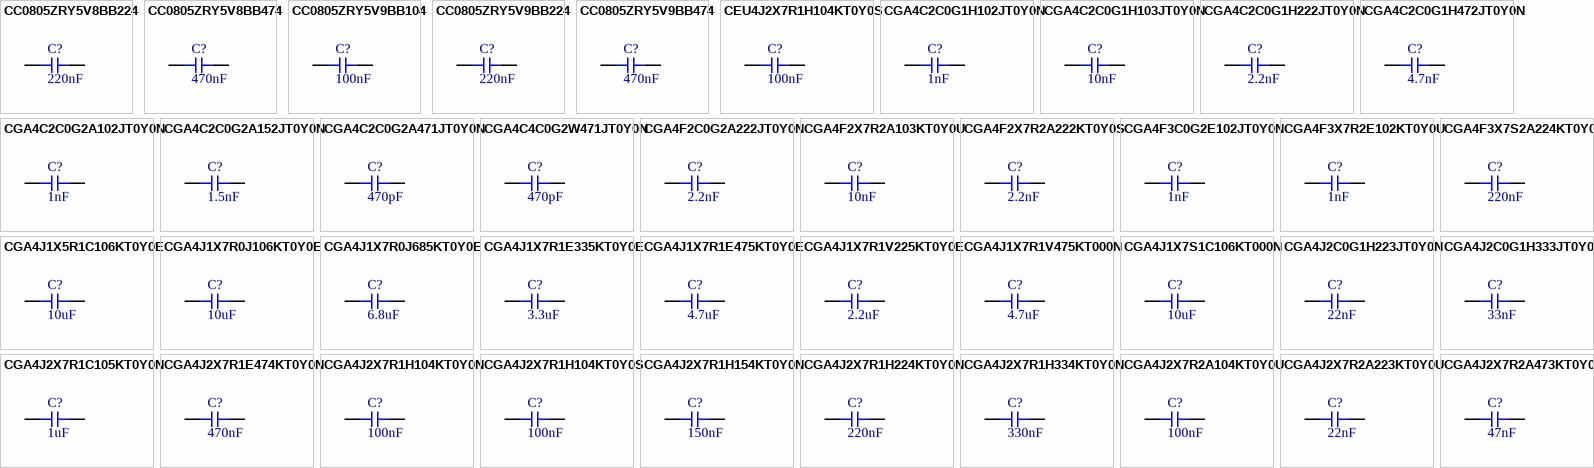
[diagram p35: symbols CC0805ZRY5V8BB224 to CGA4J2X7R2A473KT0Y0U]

## CC0805ZRY5V8BB224
designator C?  Capacitance: 220nF  (hidden comment: *)
Capacitor, Ceramic (MLCC), 220nF, 25V, Y5V, SMD 0805; Manufacturer: YAGEO; Manufacturer Part Number: CC0805ZRY5V8BB224; Temperature Rating: -20%~+80%
footprint CAP-0805 (0805 (2012M) Capacitor)
pins: 1, 2

## CC0805ZRY5V8BB474
designator C?  Capacitance: 470nF  (hidden comment: *)
Capacitor, Ceramic (MLCC), 470nF, 25V, Y5V, SMD 0805; Manufacturer: YAGEO; Manufacturer Part Number: CC0805ZRY5V8BB474; Temperature Rating: -20%~+80%
footprint CAP-0805 (0805 (2012M) Capacitor)
pins: 1, 2

## CC0805ZRY5V9BB104
designator C?  Capacitance: 100nF  (hidden comment: *)
Capacitor, Ceramic (MLCC), 100nF, 50V, Y5V, SMD 0805; Manufacturer: YAGEO; Manufacturer Part Number: CC0805ZRY5V9BB104; Temperature Rating: -20%~+80%
footprint CAP-0805 (0805 (2012M) Capacitor)
pins: 1, 2

## CC0805ZRY5V9BB224
designator C?  Capacitance: 220nF  (hidden comment: *)
Capacitor, Ceramic (MLCC), 220nF, 50V, Y5V, SMD 0805; Manufacturer: YAGEO; Manufacturer Part Number: CC0805ZRY5V9BB224; Temperature Rating: -20%~+80%
footprint CAP-0805 (0805 (2012M) Capacitor)
pins: 1, 2

## CC0805ZRY5V9BB474
designator C?  Capacitance: 470nF  (hidden comment: *)
Capacitor, Ceramic (MLCC), 470nF, 50V, Y5V, SMD 0805; Manufacturer: YAGEO; Manufacturer Part Number: CC0805ZRY5V9BB474; Temperature Rating: -20%~+80%
footprint CAP-0805 (0805 (2012M) Capacitor)
pins: 1, 2

## CEU4J2X7R1H104KT0Y0S
designator C?  Capacitance: 100nF  (hidden comment: *)
Capacitor, Ceramic (MLCC), 100nF, ±10%, 50V, X7R, ±10%, SMD 0805; Manufacturer: TDK; Manufacturer Part Number: CEU4J2X7R1H104KT0Y0S
footprint CAP-0805 (0805 (2012M) Capacitor)
pins: 1, 2

## CGA4C2C0G1H102JT0Y0N
designator C?  Capacitance: 1nF  (hidden comment: *)
Capacitor, Ceramic (MLCC), 1nF, ±5%, 50V, C0G, ±5%, SMD 0805; Manufacturer: TDK; Manufacturer Part Number: CGA4C2C0G1H102JT0Y0N
footprint CAP-0805 (0805 (2012M) Capacitor)
pins: 1, 2

## CGA4C2C0G1H103JT0Y0N
designator C?  Capacitance: 10nF  (hidden comment: *)
Capacitor, Ceramic (MLCC), 10nF, ±5%, 50V, C0G, ±5%, SMD 0805; Manufacturer: TDK; Manufacturer Part Number: CGA4C2C0G1H103JT0Y0N
footprint CAP-0805 (0805 (2012M) Capacitor)
pins: 1, 2

## CGA4C2C0G1H222JT0Y0N
designator C?  Capacitance: 2.2nF  (hidden comment: *)
Capacitor, Ceramic (MLCC), 2.2nF, ±5%, 50V, C0G, ±5%, SMD 0805; Manufacturer: TDK; Manufacturer Part Number: CGA4C2C0G1H222JT0Y0N
footprint CAP-0805 (0805 (2012M) Capacitor)
pins: 1, 2

## CGA4C2C0G1H472JT0Y0N
designator C?  Capacitance: 4.7nF  (hidden comment: *)
Capacitor, Ceramic (MLCC), 4.7nF, ±5%, 50V, C0G, ±5%, SMD 0805; Manufacturer: TDK; Manufacturer Part Number: CGA4C2C0G1H472JT0Y0N
footprint CAP-0805 (0805 (2012M) Capacitor)
pins: 1, 2

## CGA4C2C0G2A102JT0Y0N
designator C?  Capacitance: 1nF  (hidden comment: *)
Capacitor, Ceramic (MLCC), 1nF, ±5%, 100V, C0G, ±5%, SMD 0805; Manufacturer: TDK; Manufacturer Part Number: CGA4C2C0G2A102JT0Y0N
footprint CAP-0805 (0805 (2012M) Capacitor)
pins: 1, 2

## CGA4C2C0G2A152JT0Y0N
designator C?  Capacitance: 1.5nF  (hidden comment: *)
Capacitor, Ceramic (MLCC), 1.5nF, ±5%, 100V, C0G, ±5%, SMD 0805; Manufacturer: TDK; Manufacturer Part Number: CGA4C2C0G2A152JT0Y0N
footprint CAP-0805 (0805 (2012M) Capacitor)
pins: 1, 2

## CGA4C2C0G2A471JT0Y0N
designator C?  Capacitance: 470pF  (hidden comment: *)
Capacitor, Ceramic (MLCC), 470pF, ±5%, 100V, C0G, ±5%, SMD 0805; Manufacturer: TDK; Manufacturer Part Number: CGA4C2C0G2A471JT0Y0N
footprint CAP-0805 (0805 (2012M) Capacitor)
pins: 1, 2

## CGA4C4C0G2W471JT0Y0N
designator C?  Capacitance: 470pF  (hidden comment: *)
Capacitor, Ceramic (MLCC), 470pF, ±5%, 450V, C0G, ±5%, SMD 0805; Manufacturer: TDK; Manufacturer Part Number: CGA4C4C0G2W471JT0Y0N
footprint CAP-0805 (0805 (2012M) Capacitor)
pins: 1, 2

## CGA4F2C0G2A222JT0Y0N
designator C?  Capacitance: 2.2nF  (hidden comment: *)
Capacitor, Ceramic (MLCC), 2.2nF, ±5%, 100V, C0G, ±5%, SMD 0805; Manufacturer: TDK; Manufacturer Part Number: CGA4F2C0G2A222JT0Y0N
footprint CAP-0805 (0805 (2012M) Capacitor)
pins: 1, 2

## CGA4F2X7R2A103KT0Y0U
designator C?  Capacitance: 10nF  (hidden comment: *)
Capacitor, Ceramic (MLCC), 10nF, ±10%, 100V, X7R, ±10%, SMD 0805; Manufacturer: TDK; Manufacturer Part Number: CGA4F2X7R2A103KT0Y0U
footprint CAP-0805 (0805 (2012M) Capacitor)
pins: 1, 2

## CGA4F2X7R2A222KT0Y0S
designator C?  Capacitance: 2.2nF  (hidden comment: *)
Capacitor, Ceramic (MLCC), 2.2nF, ±10%, 100V, X7R, ±10%, SMD 0805; Manufacturer: TDK; Manufacturer Part Number: CGA4F2X7R2A222KT0Y0S
footprint CAP-0805 (0805 (2012M) Capacitor)
pins: 1, 2

## CGA4F3C0G2E102JT0Y0N
designator C?  Capacitance: 1nF  (hidden comment: *)
Capacitor, Ceramic (MLCC), 1nF, ±5%, 250V, C0G, ±5%, SMD 0805; Manufacturer: TDK; Manufacturer Part Number: CGA4F3C0G2E102JT0Y0N
footprint CAP-0805 (0805 (2012M) Capacitor)
pins: 1, 2

## CGA4F3X7R2E102KT0Y0U
designator C?  Capacitance: 1nF  (hidden comment: *)
Capacitor, Ceramic (MLCC), 1nF, ±10%, 250V, X7R, ±10%, SMD 0805; Manufacturer: TDK; Manufacturer Part Number: CGA4F3X7R2E102KT0Y0U
footprint CAP-0805 (0805 (2012M) Capacitor)
pins: 1, 2

## CGA4F3X7S2A224KT0Y0N
designator C?  Capacitance: 220nF  (hidden comment: *)
Capacitor, Ceramic (MLCC), 220nF, ±10%, 100V, X7S, ±10%, SMD 0805; Manufacturer: TDK; Manufacturer Part Number: CGA4F3X7S2A224KT0Y0N
footprint CAP-0805 (0805 (2012M) Capacitor)
pins: 1, 2

## CGA4J1X5R1C106KT0Y0E
designator C?  Capacitance: 10uF  (hidden comment: *)
Capacitor, Ceramic (MLCC), 10uF, ±10%, 16V, X5R, ±10%, SMD 0805; Manufacturer: TDK; Manufacturer Part Number: CGA4J1X5R1C106KT0Y0E
footprint CAP-0805 (0805 (2012M) Capacitor)
pins: 1, 2

## CGA4J1X7R0J106KT0Y0E
designator C?  Capacitance: 10uF  (hidden comment: *)
Capacitor, Ceramic (MLCC), 10uF, ±10%, 6.3V, X7R, ±10%, SMD 0805; Manufacturer: TDK; Manufacturer Part Number: CGA4J1X7R0J106KT0Y0E
footprint CAP-0805 (0805 (2012M) Capacitor)
pins: 1, 2

## CGA4J1X7R0J685KT0Y0E
designator C?  Capacitance: 6.8uF  (hidden comment: *)
Capacitor, Ceramic (MLCC), 6.8uF, ±10%, 6.3V, X7R, ±10%, SMD 0805; Manufacturer: TDK; Manufacturer Part Number: CGA4J1X7R0J685KT0Y0E
footprint CAP-0805 (0805 (2012M) Capacitor)
pins: 1, 2

## CGA4J1X7R1E335KT0Y0E
designator C?  Capacitance: 3.3uF  (hidden comment: *)
Capacitor, Ceramic (MLCC), 3.3uF, ±10%, 25V, X7R, ±10%, SMD 0805; Manufacturer: TDK; Manufacturer Part Number: CGA4J1X7R1E335KT0Y0E
footprint CAP-0805 (0805 (2012M) Capacitor)
pins: 1, 2

## CGA4J1X7R1E475KT0Y0E
designator C?  Capacitance: 4.7uF  (hidden comment: *)
Capacitor, Ceramic (MLCC), 4.7uF, ±10%, 25V, X7R, ±10%, SMD 0805; Manufacturer: TDK; Manufacturer Part Number: CGA4J1X7R1E475KT0Y0E
footprint CAP-0805 (0805 (2012M) Capacitor)
pins: 1, 2

## CGA4J1X7R1V225KT0Y0E
designator C?  Capacitance: 2.2uF  (hidden comment: *)
Capacitor, Ceramic (MLCC), 2.2uF, ±10%, 35V, X7R, ±10%, SMD 0805; Manufacturer: TDK; Manufacturer Part Number: CGA4J1X7R1V225KT0Y0E
footprint CAP-0805 (0805 (2012M) Capacitor)
pins: 1, 2

## CGA4J1X7R1V475KT000N
designator C?  Capacitance: 4.7uF  (hidden comment: *)
Capacitor, Ceramic (MLCC), 4.7uF, ±10%, 35V, X7R, ±10%, SMD 0805; Manufacturer: TDK; Manufacturer Part Number: CGA4J1X7R1V475KT000N
footprint CAP-0805 (0805 (2012M) Capacitor)
pins: 1, 2

## CGA4J1X7S1C106KT000N
designator C?  Capacitance: 10uF  (hidden comment: *)
Capacitor, Ceramic (MLCC), 10uF, ±10%, 16V, X7S, ±10%, SMD 0805; Manufacturer: TDK; Manufacturer Part Number: CGA4J1X7S1C106KT000N
footprint CAP-0805 (0805 (2012M) Capacitor)
pins: 1, 2

## CGA4J2C0G1H223JT0Y0N
designator C?  Capacitance: 22nF  (hidden comment: *)
Capacitor, Ceramic (MLCC), 22nF, ±5%, 50V, C0G, ±5%, SMD 0805; Manufacturer: TDK; Manufacturer Part Number: CGA4J2C0G1H223JT0Y0N
footprint CAP-0805 (0805 (2012M) Capacitor)
pins: 1, 2

## CGA4J2C0G1H333JT0Y0N
designator C?  Capacitance: 33nF  (hidden comment: *)
Capacitor, Ceramic (MLCC), 33nF, ±5%, 50V, C0G, ±5%, SMD 0805; Manufacturer: TDK; Manufacturer Part Number: CGA4J2C0G1H333JT0Y0N
footprint CAP-0805 (0805 (2012M) Capacitor)
pins: 1, 2

## CGA4J2X7R1C105KT0Y0N
designator C?  Capacitance: 1uF  (hidden comment: *)
Capacitor, Ceramic (MLCC), 1uF, ±10%, 16V, X7R, ±10%, SMD 0805; Manufacturer: TDK; Manufacturer Part Number: CGA4J2X7R1C105KT0Y0N
footprint CAP-0805 (0805 (2012M) Capacitor)
pins: 1, 2

## CGA4J2X7R1E474KT0Y0N
designator C?  Capacitance: 470nF  (hidden comment: *)
Capacitor, Ceramic (MLCC), 470nF, ±10%, 25V, X7R, ±10%, SMD 0805; Manufacturer: TDK; Manufacturer Part Number: CGA4J2X7R1E474KT0Y0N
footprint CAP-0805 (0805 (2012M) Capacitor)
pins: 1, 2

## CGA4J2X7R1H104KT0Y0N
designator C?  Capacitance: 100nF  (hidden comment: *)
Capacitor, Ceramic (MLCC), 100nF, ±10%, 50V, X7R, ±10%, SMD 0805; Manufacturer: TDK; Manufacturer Part Number: CGA4J2X7R1H104KT0Y0N
footprint CAP-0805 (0805 (2012M) Capacitor)
pins: 1, 2

## CGA4J2X7R1H104KT0Y0S
designator C?  Capacitance: 100nF  (hidden comment: *)
Capacitor, Ceramic (MLCC), 100nF, ±10%, 50V, X7R, ±10%, SMD 0805; Manufacturer: TDK; Manufacturer Part Number: CGA4J2X7R1H104KT0Y0S
footprint CAP-0805 (0805 (2012M) Capacitor)
pins: 1, 2

## CGA4J2X7R1H154KT0Y0N
designator C?  Capacitance: 150nF  (hidden comment: *)
Capacitor, Ceramic (MLCC), 150nF, ±10%, 50V, X7R, ±10%, SMD 0805; Manufacturer: TDK; Manufacturer Part Number: CGA4J2X7R1H154KT0Y0N
footprint CAP-0805 (0805 (2012M) Capacitor)
pins: 1, 2

## CGA4J2X7R1H224KT0Y0N
designator C?  Capacitance: 220nF  (hidden comment: *)
Capacitor, Ceramic (MLCC), 220nF, ±10%, 50V, X7R, ±10%, SMD 0805; Manufacturer: TDK; Manufacturer Part Number: CGA4J2X7R1H224KT0Y0N
footprint CAP-0805 (0805 (2012M) Capacitor)
pins: 1, 2

## CGA4J2X7R1H334KT0Y0N
designator C?  Capacitance: 330nF  (hidden comment: *)
Capacitor, Ceramic (MLCC), 330nF, ±10%, 50V, X7R, ±10%, SMD 0805; Manufacturer: TDK; Manufacturer Part Number: CGA4J2X7R1H334KT0Y0N
footprint CAP-0805 (0805 (2012M) Capacitor)
pins: 1, 2

## CGA4J2X7R2A104KT0Y0U
designator C?  Capacitance: 100nF  (hidden comment: *)
Capacitor, Ceramic (MLCC), 100nF, ±10%, 100V, X7R, ±10%, SMD 0805; Manufacturer: TDK; Manufacturer Part Number: CGA4J2X7R2A104KT0Y0U
footprint CAP-0805 (0805 (2012M) Capacitor)
pins: 1, 2

## CGA4J2X7R2A223KT0Y0U
designator C?  Capacitance: 22nF  (hidden comment: *)
Capacitor, Ceramic (MLCC), 22nF, ±10%, 100V, X7R, ±10%, SMD 0805; Manufacturer: TDK; Manufacturer Part Number: CGA4J2X7R2A223KT0Y0U
footprint CAP-0805 (0805 (2012M) Capacitor)
pins: 1, 2

## CGA4J2X7R2A473KT0Y0U
designator C?  Capacitance: 47nF  (hidden comment: *)
Capacitor, Ceramic (MLCC), 47nF, ±10%, 100V, X7R, ±10%, SMD 0805; Manufacturer: TDK; Manufacturer Part Number: CGA4J2X7R2A473KT0Y0U
footprint CAP-0805 (0805 (2012M) Capacitor)
pins: 1, 2

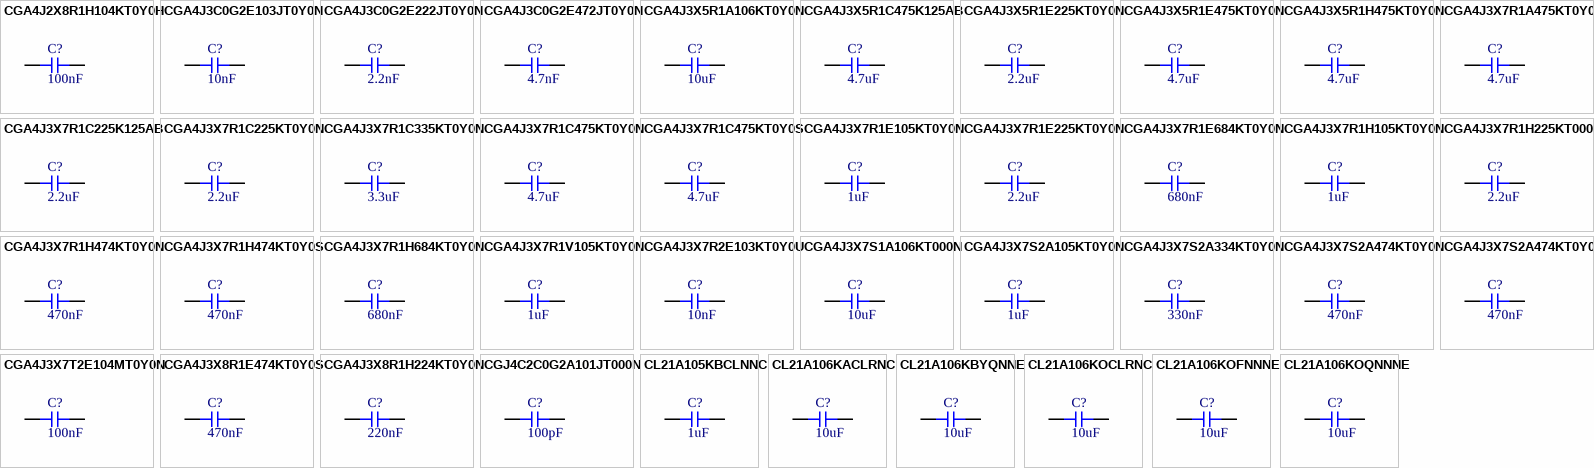
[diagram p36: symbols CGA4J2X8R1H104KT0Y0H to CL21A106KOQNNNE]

## CGA4J2X8R1H104KT0Y0H
designator C?  Capacitance: 100nF  (hidden comment: *)
Capacitor, Ceramic (MLCC), 100nF, ±10%, 50V, X8R, ±10%, SMD 0805; Manufacturer: TDK; Manufacturer Part Number: CGA4J2X8R1H104KT0Y0H
footprint CAP-0805 (0805 (2012M) Capacitor)
pins: 1, 2

## CGA4J3C0G2E103JT0Y0N
designator C?  Capacitance: 10nF  (hidden comment: *)
Capacitor, Ceramic (MLCC), 10nF, ±5%, 250V, C0G, ±5%, SMD 0805; Manufacturer: TDK; Manufacturer Part Number: CGA4J3C0G2E103JT0Y0N
footprint CAP-0805 (0805 (2012M) Capacitor)
pins: 1, 2

## CGA4J3C0G2E222JT0Y0N
designator C?  Capacitance: 2.2nF  (hidden comment: *)
Capacitor, Ceramic (MLCC), 2.2nF, ±5%, 250V, C0G, ±5%, SMD 0805; Manufacturer: TDK; Manufacturer Part Number: CGA4J3C0G2E222JT0Y0N
footprint CAP-0805 (0805 (2012M) Capacitor)
pins: 1, 2

## CGA4J3C0G2E472JT0Y0N
designator C?  Capacitance: 4.7nF  (hidden comment: *)
Capacitor, Ceramic (MLCC), 4.7nF, ±5%, 250V, C0G, ±5%, SMD 0805; Manufacturer: TDK; Manufacturer Part Number: CGA4J3C0G2E472JT0Y0N
footprint CAP-0805 (0805 (2012M) Capacitor)
pins: 1, 2

## CGA4J3X5R1A106KT0Y0N
designator C?  Capacitance: 10uF  (hidden comment: *)
Capacitor, Ceramic (MLCC), 10uF, ±10%, 10V, X5R, ±10%, SMD 0805; Manufacturer: TDK; Manufacturer Part Number: CGA4J3X5R1A106KT0Y0N
footprint CAP-0805 (0805 (2012M) Capacitor)
pins: 1, 2

## CGA4J3X5R1C475K125AB
designator C?  Capacitance: 4.7uF  (hidden comment: *)
Capacitor, Ceramic (MLCC), 4.7uF, ±10%, 16V, X5R, ±10%, SMD 0805; Manufacturer: TDK; Manufacturer Part Number: CGA4J3X5R1C475K125AB
footprint CAP-0805 (0805 (2012M) Capacitor)
pins: 1, 2

## CGA4J3X5R1E225KT0Y0N
designator C?  Capacitance: 2.2uF  (hidden comment: *)
Capacitor, Ceramic (MLCC), 2.2uF, ±10%, 25V, ±10%, SMD 0805; Manufacturer: TDK; Manufacturer Part Number: CGA4J3X5R1E225KT0Y0N
footprint CAP-0805 (0805 (2012M) Capacitor)
pins: 1, 2

## CGA4J3X5R1E475KT0Y0N
designator C?  Capacitance: 4.7uF  (hidden comment: *)
Capacitor, Ceramic (MLCC), 4.7uF, ±10%, 25V, X5R, ±10%, SMD 0805; Manufacturer: TDK; Manufacturer Part Number: CGA4J3X5R1E475KT0Y0N
footprint CAP-0805 (0805 (2012M) Capacitor)
pins: 1, 2

## CGA4J3X5R1H475KT0Y0N
designator C?  Capacitance: 4.7uF  (hidden comment: *)
Capacitor, Ceramic (MLCC), 4.7uF, ±10%, 50V, X5R, ±10%, SMD 0805; Manufacturer: TDK; Manufacturer Part Number: CGA4J3X5R1H475KT0Y0N
footprint CAP-0805 (0805 (2012M) Capacitor)
pins: 1, 2

## CGA4J3X7R1A475KT0Y0N
designator C?  Capacitance: 4.7uF  (hidden comment: *)
Capacitor, Ceramic (MLCC), 4.7uF, ±10%, 10V, X7R, ±10%, SMD 0805; Manufacturer: TDK; Manufacturer Part Number: CGA4J3X7R1A475KT0Y0N
footprint CAP-0805 (0805 (2012M) Capacitor)
pins: 1, 2

## CGA4J3X7R1C225K125AB
designator C?  Capacitance: 2.2uF  (hidden comment: *)
Capacitor, Ceramic (MLCC), 2.2uF, ±10%, 16V, X7R, ±10%, SMD 0805; Manufacturer: TDK; Manufacturer Part Number: CGA4J3X7R1C225K125AB
footprint CAP-0805 (0805 (2012M) Capacitor)
pins: 1, 2

## CGA4J3X7R1C225KT0Y0N
designator C?  Capacitance: 2.2uF  (hidden comment: *)
Capacitor, Ceramic (MLCC), 2.2uF, ±10%, 16V, X7R, ±10%, SMD 0805; Manufacturer: TDK; Manufacturer Part Number: CGA4J3X7R1C225KT0Y0N
footprint CAP-0805 (0805 (2012M) Capacitor)
pins: 1, 2

## CGA4J3X7R1C335KT0Y0N
designator C?  Capacitance: 3.3uF  (hidden comment: *)
Capacitor, Ceramic (MLCC), 3.3uF, ±10%, 16V, X7R, ±10%, SMD 0805; Manufacturer: TDK; Manufacturer Part Number: CGA4J3X7R1C335KT0Y0N
footprint CAP-0805 (0805 (2012M) Capacitor)
pins: 1, 2

## CGA4J3X7R1C475KT0Y0N
designator C?  Capacitance: 4.7uF  (hidden comment: *)
Capacitor, Ceramic (MLCC), 4.7uF, ±10%, 16V, X7R, ±10%, SMD 0805; Manufacturer: TDK; Manufacturer Part Number: CGA4J3X7R1C475KT0Y0N
footprint CAP-0805 (0805 (2012M) Capacitor)
pins: 1, 2

## CGA4J3X7R1C475KT0Y0S
designator C?  Capacitance: 4.7uF  (hidden comment: *)
Capacitor, Ceramic (MLCC), 4.7uF, ±10%, 16V, X7R, ±10%, SMD 0805; Manufacturer: TDK; Manufacturer Part Number: CGA4J3X7R1C475KT0Y0S
footprint CAP-0805 (0805 (2012M) Capacitor)
pins: 1, 2

## CGA4J3X7R1E105KT0Y0N
designator C?  Capacitance: 1uF  (hidden comment: *)
Capacitor, Ceramic (MLCC), 1uF, ±10%, 25V, X7R, ±10%, SMD 0805; Manufacturer: TDK; Manufacturer Part Number: CGA4J3X7R1E105KT0Y0N
footprint CAP-0805 (0805 (2012M) Capacitor)
pins: 1, 2

## CGA4J3X7R1E225KT0Y0N
designator C?  Capacitance: 2.2uF  (hidden comment: *)
Capacitor, Ceramic (MLCC), 2.2uF, ±10%, 25V, X7R, ±10%, SMD 0805; Manufacturer: TDK; Manufacturer Part Number: CGA4J3X7R1E225KT0Y0N
footprint CAP-0805 (0805 (2012M) Capacitor)
pins: 1, 2

## CGA4J3X7R1E684KT0Y0N
designator C?  Capacitance: 680nF  (hidden comment: *)
Capacitor, Ceramic (MLCC), 680nF, ±10%, 25V, X7R, ±10%, SMD 0805; Manufacturer: TDK; Manufacturer Part Number: CGA4J3X7R1E684KT0Y0N
footprint CAP-0805 (0805 (2012M) Capacitor)
pins: 1, 2

## CGA4J3X7R1H105KT0Y0N
designator C?  Capacitance: 1uF  (hidden comment: *)
Capacitor, Ceramic (MLCC), 1uF, ±10%, 50V, X7R, ±10%, SMD 0805; Manufacturer: TDK; Manufacturer Part Number: CGA4J3X7R1H105KT0Y0N
footprint CAP-0805 (0805 (2012M) Capacitor)
pins: 1, 2

## CGA4J3X7R1H225KT000N
designator C?  Capacitance: 2.2uF  (hidden comment: *)
Capacitor, Ceramic (MLCC), 2.2uF, ±10%, 50V, X7R, ±10%, SMD 0805; Manufacturer: TDK; Manufacturer Part Number: CGA4J3X7R1H225KT000N
footprint CAP-0805 (0805 (2012M) Capacitor)
pins: 1, 2

## CGA4J3X7R1H474KT0Y0N
designator C?  Capacitance: 470nF  (hidden comment: *)
Capacitor, Ceramic (MLCC), 470nF, ±10%, 50V, X7R, ±10%, SMD 0805; Manufacturer: TDK; Manufacturer Part Number: CGA4J3X7R1H474KT0Y0N
footprint CAP-0805 (0805 (2012M) Capacitor)
pins: 1, 2

## CGA4J3X7R1H474KT0Y0S
designator C?  Capacitance: 470nF  (hidden comment: *)
Capacitor, Ceramic (MLCC), 470nF, ±10%, 50V, X7R, ±10%, SMD 0805; Manufacturer: TDK; Manufacturer Part Number: CGA4J3X7R1H474KT0Y0S
footprint CAP-0805 (0805 (2012M) Capacitor)
pins: 1, 2

## CGA4J3X7R1H684KT0Y0N
designator C?  Capacitance: 680nF  (hidden comment: *)
Capacitor, Ceramic (MLCC), 680nF, ±10%, 50V, X7R, ±10%, SMD 0805; Manufacturer: TDK; Manufacturer Part Number: CGA4J3X7R1H684KT0Y0N
footprint CAP-0805 (0805 (2012M) Capacitor)
pins: 1, 2

## CGA4J3X7R1V105KT0Y0N
designator C?  Capacitance: 1uF  (hidden comment: *)
Capacitor, Ceramic (MLCC), 1uF, ±10%, 35V, X7R, ±10%, SMD 0805; Manufacturer: TDK; Manufacturer Part Number: CGA4J3X7R1V105KT0Y0N
footprint CAP-0805 (0805 (2012M) Capacitor)
pins: 1, 2

## CGA4J3X7R2E103KT0Y0U
designator C?  Capacitance: 10nF  (hidden comment: *)
Capacitor, Ceramic (MLCC), 10nF, ±10%, 250V, X7R, ±10%, SMD 0805; Manufacturer: TDK; Manufacturer Part Number: CGA4J3X7R2E103KT0Y0U
footprint CAP-0805 (0805 (2012M) Capacitor)
pins: 1, 2

## CGA4J3X7S1A106KT000N
designator C?  Capacitance: 10uF  (hidden comment: *)
Capacitor, Ceramic (MLCC), 10uF, ±10%, 10V, X7S, ±10%, SMD 0805; Manufacturer: TDK; Manufacturer Part Number: CGA4J3X7S1A106KT000N
footprint CAP-0805 (0805 (2012M) Capacitor)
pins: 1, 2

## CGA4J3X7S2A105KT0Y0N
designator C?  Capacitance: 1uF  (hidden comment: *)
Capacitor, Ceramic (MLCC), 1uF, ±10%, 100V, X7S, ±10%, SMD 0805; Manufacturer: TDK; Manufacturer Part Number: CGA4J3X7S2A105KT0Y0N
footprint CAP-0805 (0805 (2012M) Capacitor)
pins: 1, 2

## CGA4J3X7S2A334KT0Y0N
designator C?  Capacitance: 330nF  (hidden comment: *)
Capacitor, Ceramic (MLCC), 330nF, ±10%, 100V, X7S, ±10%, SMD 0805; Manufacturer: TDK; Manufacturer Part Number: CGA4J3X7S2A334KT0Y0N
footprint CAP-0805 (0805 (2012M) Capacitor)
pins: 1, 2

## CGA4J3X7S2A474KT0Y0N
designator C?  Capacitance: 470nF  (hidden comment: *)
Capacitor, Ceramic (MLCC), 470nF, ±10%, 100V, X7S, ±10%, SMD 0805; Manufacturer: TDK; Manufacturer Part Number: CGA4J3X7S2A474KT0Y0N
footprint CAP-0805 (0805 (2012M) Capacitor)
pins: 1, 2

## CGA4J3X7S2A474KT0Y0S
designator C?  Capacitance: 470nF  (hidden comment: *)
Capacitor, Ceramic (MLCC), 470nF, ±10%, 100V, X7S, ±10%, SMD 0805; Manufacturer: TDK; Manufacturer Part Number: CGA4J3X7S2A474KT0Y0S
footprint CAP-0805 (0805 (2012M) Capacitor)
pins: 1, 2

## CGA4J3X7T2E104MT0Y0N
designator C?  Capacitance: 100nF  (hidden comment: *)
Capacitor, Ceramic (MLCC), 100nF, ±20%, 250V, X7T, ±20%, SMD 0805; Manufacturer: TDK; Manufacturer Part Number: CGA4J3X7T2E104MT0Y0N
footprint CAP-0805 (0805 (2012M) Capacitor)
pins: 1, 2

## CGA4J3X8R1E474KT0Y0S
designator C?  Capacitance: 470nF  (hidden comment: *)
Capacitor, Ceramic (MLCC), 470nF, ±10%, 25V, X8R, ±10%, SMD 0805; Manufacturer: TDK; Manufacturer Part Number: CGA4J3X8R1E474KT0Y0S
footprint CAP-0805 (0805 (2012M) Capacitor)
pins: 1, 2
